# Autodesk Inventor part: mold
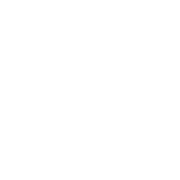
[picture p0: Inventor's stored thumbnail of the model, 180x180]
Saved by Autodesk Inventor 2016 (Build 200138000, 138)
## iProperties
Created: 2015-06
Part Number: mold
Material: Generic
Document SubType Name: Modeling
Designer: Mohamed
Density: 1 g/cm^3
Appearance: Default
Author: Mohamed
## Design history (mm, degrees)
sketch "Sketch1"
  geometry: L1 (278.503, -324.566)-(278.503, -324.249); L2 (278.503, -324.249)-(278.503, -323.98); L3 (278.503, -323.98)-(278.503, -323.712); L4 (278.503, -323.712)-(278.501, -320.016); L5 (278.501, -320.016)-(278.482, -316.319); L6 (278.482, -316.319)-(278.512, -312.624); L7 (278.512, -312.624)-(278.518, -311.914); L8 (278.518, -311.914)-(278.305, -311.38); L9 (278.305, -311.38)-(277.877, -310.825); L10 (277.877, -310.825)-(274.184, -306.037); L11 (274.184, -306.037)-(271.646, -300.705); L12 (271.646, -300.705)-(270.618, -294.726); L13 (270.618, -294.726)-(269.912, -290.617); L14 (269.912, -290.617)-(269.91, -286.515); L15 (269.91, -286.515)-(271.404, -282.536); L16 (271.404, -282.536)-(272.734, -278.992); L17 (272.734, -278.992)-(274.984, -276.278); L18 (274.984, -276.278)-(278.582, -274.855); L19 (278.582, -274.855)-(281.479, -273.71); L20 (281.479, -273.71)-(284.431, -273.782); L21 (284.431, -273.782)-(287.397, -274.574); L22 (287.397, -274.574)-(291.278, -275.61); L23 (291.278, -275.61)-(294.61, -277.652); L24 (294.61, -277.652)-(297.558, -280.313); L25 (297.558, -280.313)-(303.288, -285.487); L26 (303.288, -285.487)-(307.05, -291.866); L27 (307.05, -291.866)-(308.893, -299.355); L28 (308.893, -299.355)-(309.831, -303.17); L29 (309.831, -303.17)-(310.076, -307.034); L30 (310.076, -307.034)-(309.228, -310.909); L31 (309.228, -310.909)-(308.448, -314.475); L32 (308.448, -314.475)-(306.851, -317.556); L33 (306.851, -317.556)-(303.816, -319.749); L34 (303.816, -319.749)-(303.216, -320.183); L35 (303.216, -320.183)-(302.592, -320.585); L36 (302.592, -320.585)-(301.904, -320.858); L37 (301.904, -320.858)-(301.474, -321.029); L38 (301.474, -321.029)-(301.29, -321.29); L39 (301.29, -321.29)-(301.339, -321.741); L40 (301.339, -321.741)-(301.356, -321.895); L41 (301.356, -321.895)-(301.342, -322.052); L42 (301.342, -322.052)-(301.342, -322.208); L43 (301.342, -322.208)-(301.341, -327.109); L44 (301.341, -327.109)-(301.362, -332.012); L45 (301.362, -332.012)-(301.321, -336.914); L46 (301.321, -336.914)-(301.314, -337.724); L47 (301.314, -337.724)-(301.572, -338.175); L48 (301.572, -338.175)-(302.265, -338.568); L49 (302.265, -338.568)-(306.658, -341.062); L50 (306.658, -341.062)-(311.02, -343.61); L51 (311.02, -343.61)-(315.417, -346.097); L52 (315.417, -346.097)-(316.156, -346.515); L53 (316.156, -346.515)-(316.45, -346.991); L54 (316.45, -346.991)-(316.419, -347.842); L55 (316.419, -347.842)-(316.355, -349.59); L56 (316.355, -349.59)-(316.409, -351.343); L57 (316.409, -351.343)-(316.394, -353.094); L58 (316.394, -353.094)-(316.387, -353.985); L59 (316.387, -353.985)-(316.366, -354.022); L60 (316.366, -354.022)-(315.465, -353.98); L61 (315.465, -353.98)-(312.942, -353.865); L62 (312.942, -353.865)-(310.426, -353.642); L63 (310.426, -353.642)-(307.928, -353.264); L64 (307.928, -353.264)-(300.064, -352.072)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; 1 further point
  constraints: 3 other
extrude "Extrusion1" new body sketch "Sketch1" distance "d0" = 10; taper "d1" = 0 deg
sketch "Sketch3"
  geometry: L1 (0.533, 108.871)-(347.667, 108.871); L2 (347.667, 108.871)-(347.667, -29.221); L3 (347.667, -29.221)-(0.533, -29.221); L4 (0.533, -29.221)-(0.533, 108.871); L5 (54.028, 103.645)-(95.891, 79.475); L6 (95.891, 79.475)-(95.891, 31.136); L7 (95.891, 31.136)-(54.028, 6.967); L8 (54.028, 6.967)-(12.165, 31.136); L9 (12.165, 31.136)-(12.165, 79.475); L10 (40.338, 95.741)-(46.428, 92.224); L11 (26.749, 87.895)-(35.009, 83.127); L12 (12.165, 79.475)-(26.749, 87.895); L13 (40.338, 95.741)-(54.028, 103.645); L14 (39.444, 15.387)-(39.444, 24.924); L15 (25.855, 23.232)-(25.855, 30.265); L16 (95.891, 62.635)-(87.632, 57.866); L17 (95.891, 46.944)-(89.8, 43.428); C1 r 52.771 at (54.028, 55.306); 5 further points; 4 other entities
  constraints: 26 end point, 1 centre point, 1 coincident, 1 parallel, 50 other
  dimensions: "d27" = 360 deg dimension on C1.centre point (53.149, 80.637) (derived)
  node "Image1"
body "Solid1"
